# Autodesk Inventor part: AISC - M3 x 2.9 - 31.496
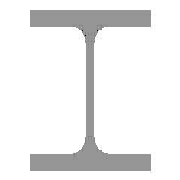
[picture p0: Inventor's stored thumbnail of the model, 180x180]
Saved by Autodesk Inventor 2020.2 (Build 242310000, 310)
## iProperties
Created: 2020-01
Part Number: AISC - M3 x 2.9 - 31.496
Material: Steel, Mild
Description: M-Shape
Document SubType Name: Modeling
Standard: ANSI
Designer: thira
Standards Organization: ANSI
Language: en-US
Size Designation: M3 x 2.9
Categories: <MemberInstance><Categories><Category DisplayName="Structural Shapes" InternalName="089c4875-fa83-4c05-b084-43b9cc11f5ed" Mnemonic="GRDR"><CategoryParameter Dis
Stock Number: M3 x 2.9
Density: 7.85 g/cm^3
Appearance: Semi-Polished
_CCFamilyMember: 14
_CCFamilyDisplayName: ANSI M - M-Shape — Sizes in parentheses have been withdrawn
_FrameMemberDoc: Frame Member File
_Version: 15.0.0
_GetPNFromCC: 1
G_L: 31.496 in
G_W: 2.250 in
G_H: 3.000 in
IsCustomPart: 1
Author: thira
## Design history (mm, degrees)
node "Start Plane"
node "End Plane"
sketch "Sketch"
  geometry: L1 (-28.575, -38.1)-(-28.575, -34.798); L2 (-28.575, -34.798)-(-10.541, -34.798); L3 (-1.143, -25.4)-(-1.143, 0); L4 (-1.143, 0)-(0, 0); L5 (0, 0)-(0, -38.1); L6 (0, -38.1)-(-28.575, -38.1); L7 (-60, 0)-(80, 0); L8 (0, -60)-(0, 80); L9 (28.575, -38.1)-(28.575, -34.798); L10 (28.575, -34.798)-(10.541, -34.798); L11 (0, -38.1)-(28.575, -38.1); L12 (1.143, -25.4)-(1.143, 0); L13 (1.143, 0)-(0, 0); L14 (-28.575, 38.1)-(-28.575, 34.798); L15 (0, 38.1)-(-28.575, 38.1); L16 (0, 38.1)-(28.575, 38.1); L17 (28.575, 34.798)-(10.541, 34.798); L18 (-28.575, 34.798)-(-10.541, 34.798); L19 (1.143, 25.4)-(1.143, 0); L20 (-1.143, 25.4)-(-1.143, 0); L21 (28.575, 38.1)-(28.575, 34.798); L22 (0, 108)-(0, -88) reference; L23 (-88, 0)-(108, 0) reference; A1 r 9.398 centre (-10.541, 25.4) between (-1.143, 25.4) and (-10.541, 34.798); A2 r 9.398 centre (10.541, 25.4) between (10.541, 34.798) and (1.143, 25.4); A3 r 9.398 centre (10.541, -25.4) between (1.143, -25.4) and (10.541, -34.798); A4 r 9.398 centre (-10.541, -25.4) between (-10.541, -34.798) and (-1.143, -25.4); 4 further points
  constraints: 42 end point, 11 symmetric about line, 8 point on circle, 8 point on line, 8 tangent, 4 centre point, 4 collinear, 4 parallel, 3 equal radius, 1 perpendicular, 1 vertical, 13 other
  dimensions: "d1" = 38.1 vertical distance of L1.start L3.end (= 0.5 x G_H); "d2" = 3.302 distance between parallel lines of L2 L6 (= G_T1); "d3" = 28.575 distance from line of L5.end L1 (= 0.5 x G_W); "d4" = 1.143 distance between parallel lines of L5 L3 (= 0.5 x G_T); "d13" = 9.398 radius of A1 (= G_IR)
extrude "Body" new body sketch "Sketch" stored distance "d5" = 800 (= G_L); taper "d6" = 0 deg
node "Driven Length"
  sketch "Sketch4"
    geometry: L1 (0, 0)-(10, 0) reference
    constraints: 2 end point, 1 horizontal
  workplane "Work Plane3"
  sketch "Sketch5"
    geometry: L1 (-2, 0)-(12, 0) reference; L2 (-2, 800)-(12, 800) reference
    dimensions: "d15" = 800 distance between parallel lines of L1 L2 (derived)
body "Solid1"
other parameters: "G_W" = 57.15 [user parameter; used in 1 equation term], "G_H" = 76.2 [user parameter; used in 1 equation term], "G_T" = 2.286 [user parameter; used in 1 equation term], "G_T1" = 3.302 [user parameter; used in 1 equation term], "G_IR" = 9.398 [user parameter; used in 1 equation term], "G_L" = 800 (= d15) [user parameter; used in 1 equation term], "G_OFFSET_START" = 0 [user parameter; used in 1 equation term], "G_OFFSET_END" = 0 [user parameter; used in 1 equation term], "d11" = 0 (computed from G_OFFSET_START), "d12" = 800 (= G_OFFSET_END + B_L), "B_L" = 800 [user parameter; used in 1 equation term], "d14" = 90 deg
